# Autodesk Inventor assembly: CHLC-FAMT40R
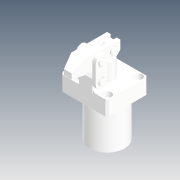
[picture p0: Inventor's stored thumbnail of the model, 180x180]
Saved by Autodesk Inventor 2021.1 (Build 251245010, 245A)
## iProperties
Created: 2019-04
Part Number: CHLC-FAMT40R
Description: STEP AP214
Document SubType Name: Assembly
Designer: user
Title: CHLC-FAMT40R.STEP
Revision Number: ÈÎºÎ
Sending System: SolidWorks 2016
Preprocessor: SwSTEP 2.0
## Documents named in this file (11)
- D:\Vault_2016\Projekty\Clamptek\Hydraulic\CHLC\CHLC-40\Inventor\CHLC-FAMT40R\CHLC-FAMT40R.iam
- D:\Vault_2016\Projekty\Clamptek\Hydraulic\CHLC\CHLC-40\Inventor\CHLC-FAMT40R\benti.ipt
- D:\Vault_2016\Projekty\Clamptek\Hydraulic\CHLC\CHLC-40\Inventor\CHLC-FAMT40R\CHLC-40-01.ipt
- D:\Vault_2016\Projekty\Clamptek\Hydraulic\CHLC\CHLC-40\Inventor\CHLC-FAMT40R\CHLC-40-02.ipt
- D:\Vault_2016\Projekty\Clamptek\Hydraulic\CHLC\CHLC-40\Inventor\CHLC-FAMT40R\CHLC-40-03.ipt
- D:\Vault_2016\Projekty\Clamptek\Hydraulic\CHLC\CHLC-40\Inventor\CHLC-FAMT40R\CHLC-40-04.ipt
- D:\Vault_2016\Projekty\Clamptek\Hydraulic\CHLC\CHLC-40\Inventor\CHLC-FAMT40R\CHLC-40-06.ipt
- D:\Vault_2016\Projekty\Clamptek\Hydraulic\CHLC\CHLC-40\Inventor\CHLC-FAMT40R\CHLC-40-08.ipt
- D:\Vault_2016\Projekty\Clamptek\Hydraulic\CHLC\CHLC-40\Inventor\CHLC-FAMT40R\CZL20µ÷ËÙ·§.iam
- D:\Vault_2016\Projekty\Clamptek\Hydraulic\CHLC\CHLC-40\Inventor\CHLC-FAMT40R\M6LS.ipt
- D:\Vault_2016\Projekty\Clamptek\Hydraulic\CHLC\CHLC-40\Inventor\CHLC-FAMT40R\ZHIC.ipt
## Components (19 placed, 19 different names)
1. benti_1
2. CHLC-40-01_2
3. CHLC-40-02_3
4. CHLC-40-03_4
5. CHLC-40-04_5
6. CHLC-40-06_6
7. CHLC-40-08_7
8. CZL20µ÷ËÙ·§_8 [sub-assembly]
9. M6LS_9
10. ZHIC_10
11. CHLC-40-03_11
12. CHLC-40-06_12
13. CHLC-40-06_13
14. CHLC-40-06_14
15. CHLC-40-06_15
16. CHLC-40-06_16
17. CHLC-40-02_17
18. M6LS_18
19. M6LS_19
